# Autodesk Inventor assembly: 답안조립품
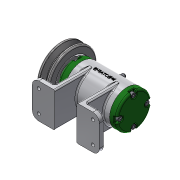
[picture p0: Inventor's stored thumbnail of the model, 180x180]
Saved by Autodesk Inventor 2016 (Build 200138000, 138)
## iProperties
Created: 2017-02
Part Number: 답안조립품
Material: 일반
Document SubType Name: Assembly
Designer: H
Author: H
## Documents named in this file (16)
- C:\Users\CAMTIC\Desktop\470207V1012\답안조립품.iam
- C:\Users\CAMTIC\Desktop\470207V1012\본체.ipt
- C:\Users\CAMTIC\Desktop\470207V1012\V벨트풀리.ipt
- C:\Users\CAMTIC\Desktop\470207V1012\너트 M 8.ipt
- C:\Users\CAMTIC\Desktop\470207V1012\니플 M 6 x 0.75.ipt
- C:\Users\CAMTIC\Desktop\470207V1012\뒤커버.ipt
- C:\Users\CAMTIC\Desktop\470207V1012\베어링 15 x 32 x 9.ipt
- C:\Users\CAMTIC\Desktop\470207V1012\볼트 M 6 x 8.ipt
- C:\Users\CAMTIC\Desktop\470207V1012\볼트 M4 x 12.ipt
- C:\Users\CAMTIC\Desktop\470207V1012\스프링와셔 8.ipt
- C:\Users\CAMTIC\Desktop\470207V1012\앞커버.ipt
- C:\Users\CAMTIC\Desktop\470207V1012\오일 실 15 25 7.ipt
- C:\Users\CAMTIC\Desktop\470207V1012\와셔 6x11.5.ipt
- C:\Users\CAMTIC\Desktop\470207V1012\와셔 8x17.ipt
- C:\Users\CAMTIC\Desktop\470207V1012\축.ipt
- C:\Users\CAMTIC\Desktop\470207V1012\키 3 x 3 x 12.ipt
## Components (11 placed, 3 different names)
1. V벨트풀리:1
2. KS B 2023 6002 - 15 x 32 x 9:1
3. KS B 2023 6002 - 15 x 32 x 9:2
4. ISO 4762 M4 x 12:1
5. ISO 4762 M4 x 12:2
6. ISO 4762 M4 x 12:3
7. ISO 4762 M4 x 12:4
8. ISO 4762 M4 x 12:5
9. ISO 4762 M4 x 12:6
10. ISO 4762 M4 x 12:7
11. ISO 4762 M4 x 12:8
